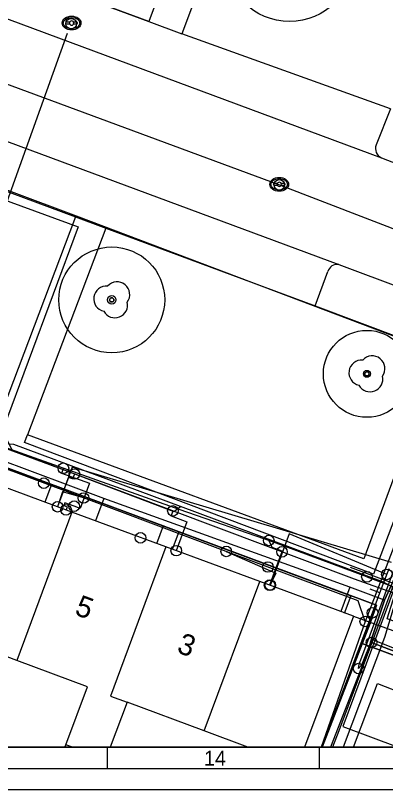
# Model space of a CAD drawing. Extents: x 192672 to 192910, y 446344 to 446512.
# Drawn here: x 192796.29 to 192813.76, y 446343.56 to 446380.14 of the extents above; entities that cross this region are included whole.
import ezdxf

# ---------------------------------------------------------------- set-up
doc = ezdxf.new("R2010")
doc.units = 0
for name, color, linetype in [('( Toegevoegd 29-11-2021 14_41_42) ondersteunend wegdeel vlak', 7, 'Continuous'), ('( Toegevoegd 29-11-2021 14_41_42) wegdeel vlak', 7, 'Continuous'), ('1010 viewport', 7, 'Continuous'), ('B-GV-GR-BOOM-S', 7, 'Continuous'), ('B-GV-KG-GRENS_WERKGRENS-G', 7, 'Continuous'), ('B-OI-KL-()_AFSLUITER_WATER-S', 7, 'Continuous'), ('B-OI-KL-()_OVERIG_RIOOLVRIJVERVAL-S', 7, 'Continuous'), ('B-OI-KL-()_PUNTVANLEVERING_WATER-S', 7, 'Continuous'), ('B-OI-KL-BUISLEIDING_OLIEGASCHEMICALIEN_GASLAGEDRUK-G', 7, 'Continuous'), ('B-OI-KL-DATA-G', 7, 'Continuous'), ('B-OI-KL-DATA_GTWP-S', 7, 'Continuous'), ('B-OI-KL-DATA_HANDHOLE-S', 7, 'Continuous'), ('B-OI-KL-DATA_KABELBED-G', 7, 'Continuous'), ('B-OI-KL-DATA_MOF-S', 7, 'Continuous'), ('B-OI-KL-ET_LS-G', 7, 'Continuous'), ('B-OI-KL-ET_LS_AARDING-S', 7, 'Continuous'), ('B-OI-KL-ET_LS_DELIVERYPOINT-S', 7, 'Continuous'), ('B-OI-KL-ET_LS_MOF-S', 7, 'Continuous'), ('B-OI-KL-GAS_LD_AFTAKZADEL-S', 7, 'Continuous'), ('B-OI-KL-GAS_LD_DELIVERYPOINT-S', 7, 'Continuous'), ('B-OI-KL-WATER-G', 7, 'Continuous'), ('B-OI-RI-RIOOLVRIJVERVAL-G', 7, 'Continuous'), ('boom', 7, 'Continuous'), ('Default', 7, 'Continuous'), ('huisnummerreeks BGT', 7, 'Continuous'), ('inspectie-   rioolput', 7, 'Continuous'), ('kant verharding', 7, 'Continuous'), ('pand op maaiveld vlak', 7, 'Continuous'), ('verkeerseiland - berm', 7, 'Continuous'), ('X-XX-AL-TEKENBLAD-S', 7, 'Continuous')]:
    doc.layers.add(name, color=color, linetype=linetype)

# ---------------------------------------------------------------- blocks, each defined once
blk = doc.blocks.new('B-OI-KL-ET_LS_AARDING-S')
at = {"layer": 'Default'}
blk.add_circle((0, 0), 0.25, dxfattribs=at)
blk = doc.blocks.new('B-OI-KL-GAS_LD_AFTAKZADEL-S')
at = {"layer": 'Default'}
blk.add_circle((0, 0), 0.25, dxfattribs=at)
blk = doc.blocks.new('B-OI-KL-GAS_LD_DELIVERYPOINT-S')
at = {"layer": 'Default'}
blk.add_circle((0, 0), 0.25, dxfattribs=at)
blk = doc.blocks.new('B-OI-KL-ET_LS_DELIVERYPOINT-S')
at = {"layer": 'Default'}
blk.add_circle((0, 0), 0.25, dxfattribs=at)
blk = doc.blocks.new('B-OI-KL-ET_LS_MOF-S')
at = {"layer": 'Default'}
blk.add_circle((0, 0), 0.25, dxfattribs=at)
blk = doc.blocks.new('B-OI-KL-DATA_HANDHOLE-S')
at = {"layer": 'Default'}
blk.add_circle((0, 0), 0.25, dxfattribs=at)
blk = doc.blocks.new('B-OI-KL-()_OVERIG_RIOOLVRIJVERVAL-S')
at = {"layer": 'Default'}
blk.add_circle((0, 0), 0.25, dxfattribs=at)
blk = doc.blocks.new('B-OI-KL-()_AFSLUITER_WATER-S')
at = {"layer": 'Default'}
blk.add_circle((0, 0), 0.25, dxfattribs=at)
blk = doc.blocks.new('B-OI-KL-()_PUNTVANLEVERING_WATER-S')
at = {"layer": 'Default'}
blk.add_circle((0, 0), 0.25, dxfattribs=at)
blk = doc.blocks.new('B-OI-KL-DATA_GTWP-S')
at = {"layer": 'Default'}
blk.add_circle((0, 0), 0.25, dxfattribs=at)
blk = doc.blocks.new('B-OI-KL-DATA_MOF-S')
at = {"layer": 'Default'}
blk.add_circle((0, 0), 0.25, dxfattribs=at)

msp = doc.modelspace()

# ---------------------------------------------------------------- linework, layer by layer
at = {"layer": '( Toegevoegd 29-11-2021 14_41_42) ondersteunend wegdeel vlak'}
for p, q in [((192810.44, 446366.419), (192811.04, 446368.034)), ((192811.557, 446368.364), (192816.34, 446366.568)), ((192810.44, 446366.419), (192816.333, 446364.188))]:
    msp.add_line(p, q, dxfattribs=at)
msp.add_arc((192811.476, 446367.92), 0.451, 79.6871, 165.4129, dxfattribs=at)
at = {"layer": '( Toegevoegd 29-11-2021 14_41_42) wegdeel vlak'}
for p, q in [((192813.567, 446373.412), (192818.683, 446371.433)), ((192812.252, 446351.747), (192816.13, 446350.319))]:
    msp.add_line(p, q, dxfattribs=at)
msp.add_lwpolyline([(192817.05, 446363.917), (192813.194, 446353.729), (192796.724, 446359.963), (192796.861, 446360.326)], dxfattribs=at)
at = {"layer": '1010 viewport'}
msp.add_lwpolyline([(192675.743, 446509.756), (192860.643, 446509.756), (192860.643, 446345.556), (192675.743, 446345.556)], close=True, dxfattribs=at)
at = {"layer": 'B-GV-GR-BOOM-S'}
for centre, radius in [((192809.234, 446382.89), 3.036), ((192800.837, 446366.698), 2.5), ((192800.837, 446366.698), 0.2), ((192812.883, 446363.201), 2.054), ((192812.883, 446363.201), 0.164)]:
    msp.add_circle(centre, radius, dxfattribs=at)
at = {"layer": 'B-GV-KG-GRENS_WERKGRENS-G'}
msp.add_lwpolyline([(192788.443, 446395.14), (192806.008, 446389.049), (192802.587, 446379.853), (192794.566, 446382.838), (192790.602, 446384.314), (192785.169, 446386.336)], close=True, dxfattribs=at)
at = {"layer": 'B-OI-KL-BUISLEIDING_OLIEGASCHEMICALIEN_GASLAGEDRUK-G'}
for points in [[(192814.329, 446352.769), (192812.29, 446353.505), (192799.482, 446358.316), (192779.419, 446365.745), (192771.402, 446368.773), (192742.155, 446379.378)], [(192799.075, 446358.467), (192798.988, 446358.232), (192798.799, 446358.302), (192798.28, 446356.918)], [(192803.724, 446356.723), (192803.636, 446356.489), (192804.386, 446356.207), (192803.882, 446354.844)], [(192808.873, 446354.789), (192808.29, 446353.214)], [(192814.329, 446352.769), (192813.707, 446350.744), (192811.759, 446345.556)]]:
    msp.add_lwpolyline(points, dxfattribs=at)
at = {"layer": 'B-OI-KL-DATA-G'}
for points in [[(192824.805, 446383.834), (192823.164, 446378.851), (192822.38, 446377.185), (192819.762, 446371.459), (192817.625, 446365.634), (192817.264, 446364.701), (192817.818, 446364.377), (192818.006, 446363.719), (192814.704, 446354.672), (192813.718, 446352.511), (192813.055, 446350.527)], [(192824.805, 446383.834), (192823.164, 446378.851), (192822.38, 446377.185), (192819.762, 446371.459), (192817.625, 446365.634), (192817.264, 446364.701), (192817.818, 446364.377), (192818.006, 446363.719), (192814.704, 446354.672), (192813.718, 446352.511)], [(192731.661, 446354.909), (192730.818, 446355.23), (192736.793, 446371.939), (192739.862, 446380.106), (192740.707, 446379.788), (192762.994, 446371.683), (192773.332, 446367.794), (192777.507, 446366.23), (192792.515, 446360.708), (192794.868, 446359.138), (192813.343, 446352.261), (192813.029, 446351.418), (192812.66, 446350.461), (192825.476, 446345.665), (192825.435, 446345.556)], [(192825.435, 446345.556), (192825.476, 446345.665), (192812.66, 446350.461), (192813.029, 446351.418), (192813.343, 446352.261), (192794.868, 446359.138), (192792.515, 446360.708), (192777.507, 446366.23), (192773.332, 446367.794), (192762.994, 446371.683), (192740.707, 446379.788), (192739.862, 446380.106), (192736.793, 446371.939), (192730.818, 446355.23), (192731.661, 446354.909)], [(192731.661, 446354.909), (192730.818, 446355.23), (192736.793, 446371.939), (192739.862, 446380.106), (192740.707, 446379.788), (192762.994, 446371.683), (192773.332, 446367.794), (192777.507, 446366.23), (192792.515, 446360.708), (192794.868, 446359.138), (192813.343, 446352.261), (192813.029, 446351.418), (192812.66, 446350.461), (192825.476, 446345.665), (192825.435, 446345.556)], [(192825.435, 446345.556), (192825.476, 446345.665), (192812.66, 446350.461), (192813.029, 446351.418), (192813.343, 446352.261), (192794.868, 446359.138), (192792.515, 446360.708), (192777.507, 446366.23), (192773.332, 446367.794), (192762.994, 446371.683), (192740.707, 446379.788), (192739.862, 446380.106), (192736.793, 446371.939), (192730.818, 446355.23), (192731.661, 446354.909)], [(192825.435, 446345.556), (192825.476, 446345.665), (192812.66, 446350.461), (192813.029, 446351.418), (192813.343, 446352.261), (192794.868, 446359.138), (192792.515, 446360.708), (192777.507, 446366.23), (192773.332, 446367.794), (192762.994, 446371.683), (192740.707, 446379.788), (192739.862, 446380.106), (192736.793, 446371.939), (192730.818, 446355.23), (192731.661, 446354.909)], [(192825.435, 446345.556), (192825.476, 446345.665), (192812.66, 446350.461), (192813.029, 446351.418), (192813.343, 446352.261), (192794.868, 446359.138), (192792.515, 446360.708), (192777.507, 446366.23), (192773.332, 446367.794), (192762.994, 446371.683), (192740.707, 446379.788), (192739.862, 446380.106), (192736.793, 446371.939), (192730.818, 446355.23), (192731.661, 446354.909)], [(192825.435, 446345.556), (192825.476, 446345.665), (192812.66, 446350.461), (192813.029, 446351.418), (192813.343, 446352.261), (192794.868, 446359.138), (192792.515, 446360.708), (192777.507, 446366.23), (192773.332, 446367.794), (192762.994, 446371.683), (192740.707, 446379.788), (192739.862, 446380.106), (192736.793, 446371.939), (192730.818, 446355.23), (192731.661, 446354.909)], [(192731.661, 446354.909), (192730.818, 446355.23), (192736.793, 446371.939), (192739.862, 446380.106), (192740.707, 446379.788), (192762.994, 446371.683), (192773.332, 446367.794), (192777.507, 446366.23), (192792.515, 446360.708), (192794.868, 446359.138), (192813.343, 446352.261), (192813.029, 446351.418), (192812.66, 446350.461), (192825.476, 446345.665), (192825.435, 446345.556)], [(192731.661, 446354.909), (192730.818, 446355.23), (192736.793, 446371.939), (192739.862, 446380.106), (192740.707, 446379.788), (192762.994, 446371.683), (192773.332, 446367.794), (192777.507, 446366.23), (192792.515, 446360.708), (192794.868, 446359.138), (192813.343, 446352.261), (192813.029, 446351.418), (192812.66, 446350.461), (192825.476, 446345.665), (192825.435, 446345.556)], [(192825.435, 446345.556), (192825.476, 446345.665), (192812.66, 446350.461), (192813.029, 446351.418), (192813.343, 446352.261), (192794.868, 446359.138), (192792.515, 446360.708), (192777.507, 446366.23), (192773.332, 446367.794), (192762.994, 446371.683), (192740.707, 446379.788), (192739.862, 446380.106), (192736.793, 446371.939), (192730.818, 446355.23), (192731.661, 446354.909)], [(192825.435, 446345.556), (192825.476, 446345.665), (192812.66, 446350.461), (192813.029, 446351.418), (192813.343, 446352.261), (192794.868, 446359.138), (192792.515, 446360.708), (192777.507, 446366.23), (192773.332, 446367.794), (192762.994, 446371.683), (192740.707, 446379.788), (192739.862, 446380.106), (192736.793, 446371.939), (192730.818, 446355.23), (192731.661, 446354.909)], [(192777.905, 446365.29), (192778.164, 446365.987), (192792.515, 446360.708), (192794.868, 446359.138), (192813.343, 446352.261), (192813.029, 446351.418), (192810.767, 446345.556)], [(192777.905, 446365.29), (192778.164, 446365.987), (192792.515, 446360.708), (192794.868, 446359.138), (192813.343, 446352.261), (192813.029, 446351.418), (192810.767, 446345.556)], [(192777.905, 446365.29), (192778.164, 446365.987), (192792.515, 446360.708), (192794.868, 446359.138), (192812.121, 446352.716), (192811.808, 446351.873)], [(192777.905, 446365.29), (192778.164, 446365.987), (192792.515, 446360.708), (192794.868, 446359.138), (192813.343, 446352.261), (192813.029, 446351.418), (192810.767, 446345.556)], [(192777.905, 446365.29), (192778.164, 446365.987), (192792.515, 446360.708), (192794.868, 446359.138), (192797.996, 446357.974), (192797.683, 446357.13)], [(192777.905, 446365.29), (192778.164, 446365.987), (192792.515, 446360.708), (192794.868, 446359.138), (192813.343, 446352.261), (192813.029, 446351.418), (192810.767, 446345.556)], [(192825.435, 446345.556), (192825.476, 446345.665), (192812.66, 446350.461), (192813.029, 446351.418), (192813.343, 446352.261), (192794.868, 446359.138), (192792.515, 446360.708), (192778.164, 446365.987), (192777.905, 446365.29)], [(192800.457, 446357.305), (192792.035, 446360.454)], [(192800.457, 446357.305), (192800.069, 446356.256)], [(192812.07, 446353.116), (192800.457, 446357.305)], [(192815.566, 446349.551), (192813.055, 446350.527), (192813.718, 446352.511), (192814.704, 446354.672)], [(192812.07, 446353.116), (192811.646, 446351.971)], [(192813.718, 446352.511), (192812.07, 446353.116)], [(192813.055, 446350.527), (192813.718, 446352.511)], [(192813.055, 446350.527), (192812.853, 446349.892), (192811.169, 446345.556)], [(192813.055, 446350.527), (192815.566, 446349.551), (192822.886, 446346.978), (192825.494, 446345.992)], [(192813.055, 446350.527), (192815.566, 446349.551), (192822.886, 446346.978), (192825.494, 446345.992), (192825.336, 446345.556)], [(192825.435, 446345.556), (192825.476, 446345.665), (192812.66, 446350.461), (192810.767, 446345.556)], [(192825.435, 446345.556), (192825.476, 446345.665), (192812.66, 446350.461), (192810.767, 446345.556)]]:
    msp.add_lwpolyline(points, dxfattribs=at)
at = {"layer": 'B-OI-KL-DATA_KABELBED-G'}
for p, q in [((192812.803, 446351.499), (192810.716, 446345.556)), ((192810.769, 446345.556), (192812.66, 446350.461))]:
    msp.add_line(p, q, dxfattribs=at)
for points in [[(192744.469, 446391.186), (192762.819, 446384.291), (192799.152, 446370.668), (192816.75, 446364.01), (192817.485, 446363.735), (192812.909, 446351.776), (192812.803, 446351.499)], [(192812.803, 446351.5), (192812.464, 446352.48), (192806.244, 446354.809), (192799.501, 446357.334), (192790.741, 446360.614), (192790.377, 446360.75), (192789.321, 446361.146), (192788.597, 446361.417), (192785.666, 446362.514), (192777.496, 446365.573), (192777.131, 446365.71), (192772.96, 446367.272), (192771.66, 446367.759), (192767.539, 446369.302), (192765.803, 446369.952), (192763.181, 446370.934), (192762.609, 446371.148), (192755.115, 446373.954), (192746.365, 446377.23), (192746.085, 446376.483)], [(192797.996, 446357.974), (192794.868, 446359.138), (192794.608, 446359.311)], [(192797.996, 446357.974), (192797.683, 446357.13)], [(192803.263, 446356.013), (192797.996, 446357.974)], [(192799.501, 446357.334), (192798.508, 446357.617), (192798.28, 446356.918)], [(192803.263, 446356.013), (192802.95, 446355.17)], [(192804.003, 446355.738), (192803.263, 446356.013)], [(192804.003, 446355.738), (192803.691, 446354.894)], [(192812.121, 446352.716), (192804.003, 446355.738)], [(192806.244, 446354.809), (192808.579, 446353.788), (192808.319, 446353.22)], [(192812.121, 446352.716), (192811.808, 446351.873)], [(192812.66, 446350.461), (192813.343, 446352.261), (192812.121, 446352.716)], [(192812.66, 446350.461), (192814.918, 446349.616)]]:
    msp.add_lwpolyline(points, dxfattribs=at)
at = {"layer": 'B-OI-KL-ET_LS-G'}
for points in [[(192860.643, 446440.124), (192852.81, 446419.045), (192841.692, 446388.528), (192838.898, 446381.453), (192837.868, 446378.608), (192831.14, 446359.912), (192827.608, 446350.172), (192825.86, 446345.608), (192823.662, 446346.45), (192813.113, 446350.64), (192812.633, 446349.432), (192812.489, 446349.272), (192812.519, 446349.474), (192812.973, 446350.693), (192815.284, 446357.022), (192818.135, 446364.563), (192821.002, 446371.788), (192821.837, 446373.928), (192823.179, 446377.806), (192823.767, 446377.593)], [(192812.885, 446353.609), (192808.475, 446355.248), (192804.025, 446356.797), (192795.126, 446359.954), (192777.441, 446366.051), (192758.408, 446373.136), (192745.69, 446378.74), (192740.34, 446380.878), (192731.982, 446384.732), (192732.765, 446387.575)], [(192792.871, 446372.473), (192799.25, 446370.149), (192795.714, 446360.605), (192795.813, 446360.209), (192796.135, 446359.591), (192803.775, 446356.698), (192804.08, 446356.938)], [(192804.08, 446356.938), (192796.209, 446359.863), (192795.739, 446359.888), (192786.071, 446363.522), (192782.511, 446364.833), (192781.93, 446364.664)], [(192798.553, 446358.738), (192798.469, 446358.503), (192799.787, 446358.035), (192799.345, 446356.843), (192799.064, 446356.947)], [(192799.064, 446356.947), (192798.627, 446357.112), (192798.58, 446356.984), (192798.735, 446356.918), (192798.679, 446356.77)], [(192823.75, 446345.886), (192824.47, 446347.92), (192813.838, 446351.629), (192814.209, 446352.816), (192814.085, 446353.113), (192813.665, 446353.36), (192804.08, 446356.938)], [(192808.249, 446355.327), (192808.39, 446355.013), (192808.914, 446354.818), (192808.313, 446353.205)], [(192812.09, 446354.065), (192814.25, 446353.262), (192811.744, 446346.534), (192814.358, 446345.556)], [(192812.885, 446353.609), (192814.103, 446353.156), (192811.563, 446346.333), (192811.258, 446345.556)]]:
    msp.add_lwpolyline(points, dxfattribs=at)
at = {"layer": 'B-OI-KL-WATER-G'}
msp.add_line((192810.761, 446345.556), (192813.146, 446351.91), dxfattribs=at)
for points in [[(192814.038, 446354.285), (192798.975, 446358.793), (192798.28, 446356.918)], [(192813.827, 446353.723), (192809.216, 446355.643), (192808.313, 446353.205)], [(192813.498, 446352.847), (192813.93, 446353.998)], [(192813.498, 446352.847), (192813.03, 446353.023)], [(192813.146, 446351.91), (192813.498, 446352.847)]]:
    msp.add_lwpolyline(points, dxfattribs=at)
at = {"layer": 'B-OI-RI-RIOOLVRIJVERVAL-G'}
for points in [[(192795.815, 446371.133), (192798.748, 446379.298)], [(192791.8, 446378.41), (192808.75, 446372.13)], [(192808.75, 446372.13), (192825.54, 446365.66)]]:
    msp.add_lwpolyline(points, dxfattribs=at)
at = {"layer": 'boom'}
for centre in [(192800.837, 446366.698), (192812.883, 446363.201)]:
    msp.add_circle(centre, 0.1, dxfattribs=at)
for centre, radius, start, end in [((192800.587, 446366.748), 0.6, 85.137, 257.7544), ((192801.087, 446366.948), 0.6, 323.5446, 138.4658), ((192800.987, 446366.448), 0.6, 208.5058, 13.8356), ((192800.837, 446366.698), 0.1, 0, 180), ((192800.837, 446366.698), 0.1, 180, 0), ((192813.133, 446363.451), 0.6, 323.5446, 138.4658), ((192812.633, 446363.251), 0.6, 85.137, 257.7544), ((192812.883, 446363.201), 0.1, 0, 180), ((192813.033, 446362.951), 0.6, 208.5058, 13.8356), ((192812.883, 446363.201), 0.1, 180, 0)]:
    msp.add_arc(centre, radius, start, end, dxfattribs=at)
at = {"layer": 'inspectie-   rioolput'}
for p, q in [((192798.847, 446379.818), (192798.69, 446379.818)), ((192798.69, 446379.742), (192798.847, 446379.742)), ((192799.19, 446379.818), (192799.033, 446379.818)), ((192799.033, 446379.742), (192799.19, 446379.742)), ((192808.65, 446372.197), (192808.493, 446372.197)), ((192808.493, 446372.122), (192808.65, 446372.122)), ((192808.993, 446372.197), (192808.836, 446372.197)), ((192808.836, 446372.122), (192808.993, 446372.122))]:
    msp.add_line(p, q, dxfattribs=at)
for centre, radius, start, end in [((192798.69, 446379.78), 0.0375, 90, 270), ((192798.94, 446379.78), 0.1, 0, 180), ((192798.94, 446379.78), 0.1, 157.9757, 180), ((192798.94, 446379.78), 0.1, 180, 202.0243), ((192798.94, 446379.78), 0.1, 180, 0), ((192798.94, 446379.78), 0.1, 0, 22.0243), ((192798.94, 446379.78), 0.1, 337.9757, 0), ((192799.19, 446379.78), 0.0375, 270, 90), ((192808.493, 446372.159), 0.0375, 90, 270), ((192808.743, 446372.159), 0.1, 0, 180), ((192808.743, 446372.159), 0.1, 157.9757, 180), ((192808.743, 446372.159), 0.1, 180, 202.0243), ((192808.743, 446372.159), 0.1, 180, 0), ((192808.743, 446372.159), 0.1, 0, 22.0243), ((192808.743, 446372.159), 0.1, 337.9757, 0), ((192808.993, 446372.159), 0.0375, 270, 90)]:
    msp.add_arc(centre, radius, start, end, dxfattribs=at)
for centre, major_axis, ratio in [((192798.94, 446379.78), (-0.442, 0), 0.73911), ((192798.94, 446379.78), (-0.392, 0), 0.689655), ((192808.743, 446372.159), (-0.442, 0), 0.73911), ((192808.743, 446372.159), (-0.392, 0), 0.689655)]:
    msp.add_ellipse(centre, major_axis=major_axis, ratio=ratio, dxfattribs=at)
at = {"layer": 'kant verharding'}
for p, q in [((192753.133, 446395.89), (192813.567, 446373.412)), ((192751.186, 446390.775), (192811.557, 446368.364)), ((192802.587, 446379.853), (192804.14, 446379.275)), ((192813.995, 446375.727), (192813.321, 446374.017)), ((192799.123, 446370.623), (192800.557, 446370.09))]:
    msp.add_line(p, q, dxfattribs=at)
msp.add_lwpolyline([(192812.242, 446345.556), (192813.378, 446348.56), (192814.757, 446348.025)], dxfattribs=at)
msp.add_arc((192813.766, 446373.846), 0.477, 158.9361, 245.3183, dxfattribs=at)
at = {"layer": 'pand op maaiveld vlak'}
for p, q in [((192798.96, 446356.666), (192794.529, 446358.306)), ((192798.96, 446356.666), (192796.362, 446349.647)), ((192803.39, 446355.026), (192798.96, 446356.666)), ((192807.821, 446353.387), (192803.39, 446355.026)), ((192805.207, 446346.322), (192807.821, 446353.387)), ((192812.252, 446351.747), (192807.821, 446353.387)), ((192812.252, 446351.747), (192809.944, 446345.556)), ((192796.362, 446349.647), (192791.933, 446351.298)), ((192801.557, 446347.683), (192800.764, 446345.556)), ((192805.207, 446346.322), (192801.557, 446347.683)), ((192807.262, 446345.556), (192805.207, 446346.322)), ((192798.628, 446345.556), (192798.671, 446345.67)), ((192798.978, 446345.556), (192798.671, 446345.67))]:
    msp.add_line(p, q, dxfattribs=at)
for points in [[(192803.39, 446355.026), (192800.779, 446347.971), (192801.557, 446347.683)], [(192798.671, 446345.67), (192799.691, 446348.406), (192796.362, 446349.647)]]:
    msp.add_lwpolyline(points, dxfattribs=at)
at = {"layer": 'verkeerseiland - berm'}
for p, q in [((192806.008, 446389.049), (192802.587, 446379.853)), ((192807.659, 446388.548), (192804.14, 446379.275)), ((192785.169, 446386.336), (192802.587, 446379.853)), ((192813.995, 446375.727), (192804.14, 446379.275)), ((192781.749, 446377.077), (192799.123, 446370.623)), ((192799.123, 446370.623), (192795.43, 446360.855)), ((192800.557, 446370.09), (192796.861, 446360.326)), ((192800.557, 446370.09), (192810.44, 446366.419))]:
    msp.add_line(p, q, dxfattribs=at)
msp.add_lwpolyline([(192816.333, 446364.188), (192812.737, 446354.452), (192796.861, 446360.326)], dxfattribs=at)
at = {"layer": 'X-XX-AL-TEKENBLAD-S'}
for p, q in [((192800.643, 446344.556), (192800.643, 446345.556)), ((192810.643, 446344.556), (192810.643, 446345.556)), ((192674.743, 446344.556), (192908.543, 446344.556)), ((192671.743, 446343.556), (192909.543, 446343.556))]:
    msp.add_line(p, q, dxfattribs=at)
msp.add_lwpolyline([(192675.743, 446345.556), (192907.543, 446345.556), (192907.543, 446509.756), (192675.743, 446509.756)], close=True, dxfattribs=at)

# ---------------------------------------------------------------- block references
at = {"layer": 'B-OI-KL-()_AFSLUITER_WATER-S'}
msp.add_blockref('B-OI-KL-()_AFSLUITER_WATER-S', (192813.146, 446351.91), dxfattribs=at)
at = {"layer": 'B-OI-KL-()_OVERIG_RIOOLVRIJVERVAL-S'}
for p in [(192798.92, 446379.75), (192808.75, 446372.13)]:
    msp.add_blockref('B-OI-KL-()_OVERIG_RIOOLVRIJVERVAL-S', p, dxfattribs=at)
at = {"layer": 'B-OI-KL-()_PUNTVANLEVERING_WATER-S'}
msp.add_blockref('B-OI-KL-()_PUNTVANLEVERING_WATER-S', (192813.827, 446353.723), dxfattribs=at)
at = {"layer": 'B-OI-KL-DATA_GTWP-S'}
for p in [(192799.501, 446357.334), (192798.28, 446356.918), (192806.244, 446354.809), (192808.319, 446353.22), (192812.803, 446351.5), (192812.803, 446351.499), (192812.803, 446351.499)]:
    msp.add_blockref('B-OI-KL-DATA_GTWP-S', p, dxfattribs=at)
at = {"layer": 'B-OI-KL-DATA_HANDHOLE-S'}
msp.add_blockref('B-OI-KL-DATA_HANDHOLE-S', (192813.1, 446350.5), dxfattribs=at)
at = {"layer": 'B-OI-KL-DATA_MOF-S'}
for p in [(192797.629, 446358.035), (192799.501, 446357.334), (192806.244, 446354.809), (192808.21, 446354.073)]:
    msp.add_blockref('B-OI-KL-DATA_MOF-S', p, dxfattribs=at)
at = {"layer": 'B-OI-KL-ET_LS_AARDING-S'}
msp.add_blockref('B-OI-KL-ET_LS_AARDING-S', (192812.489, 446349.272), dxfattribs=at)
at = {"layer": 'B-OI-KL-ET_LS_DELIVERYPOINT-S'}
for p in [(192802.194, 446355.451), (192802.194, 446355.451), (192808.313, 446353.205)]:
    msp.add_blockref('B-OI-KL-ET_LS_DELIVERYPOINT-S', p, dxfattribs=at)
at = {"layer": 'B-OI-KL-ET_LS_MOF-S'}
for p in [(192798.553, 446358.738), (192799.064, 446356.947), (192798.679, 446356.77), (192808.249, 446355.327), (192812.885, 446353.609)]:
    msp.add_blockref('B-OI-KL-ET_LS_MOF-S', p, dxfattribs=at)
at = {"layer": 'B-OI-KL-GAS_LD_AFTAKZADEL-S'}
for p in [(192799.075, 446358.467), (192803.724, 446356.723), (192808.873, 446354.789)]:
    msp.add_blockref('B-OI-KL-GAS_LD_AFTAKZADEL-S', p, dxfattribs=at)
at = {"layer": 'B-OI-KL-GAS_LD_DELIVERYPOINT-S'}
for p in [(192798.28, 446356.918), (192803.882, 446354.844), (192808.29, 446353.214)]:
    msp.add_blockref('B-OI-KL-GAS_LD_DELIVERYPOINT-S', p, dxfattribs=at)

# ---------------------------------------------------------------- texts
at = {"layer": 'huisnummerreeks BGT'}
for s, p in [('5', (192799.037, 446351.839)), ('3', (192803.861, 446350.054))]:
    msp.add_text(s, height=1, rotation=339.7, dxfattribs=at).set_placement(p)
at = {"layer": 'X-XX-AL-TEKENBLAD-S'}
msp.add_text('14', height=0.7, dxfattribs=at).set_placement((192805.189, 446344.685))

doc.saveas('drawing.dxf')
